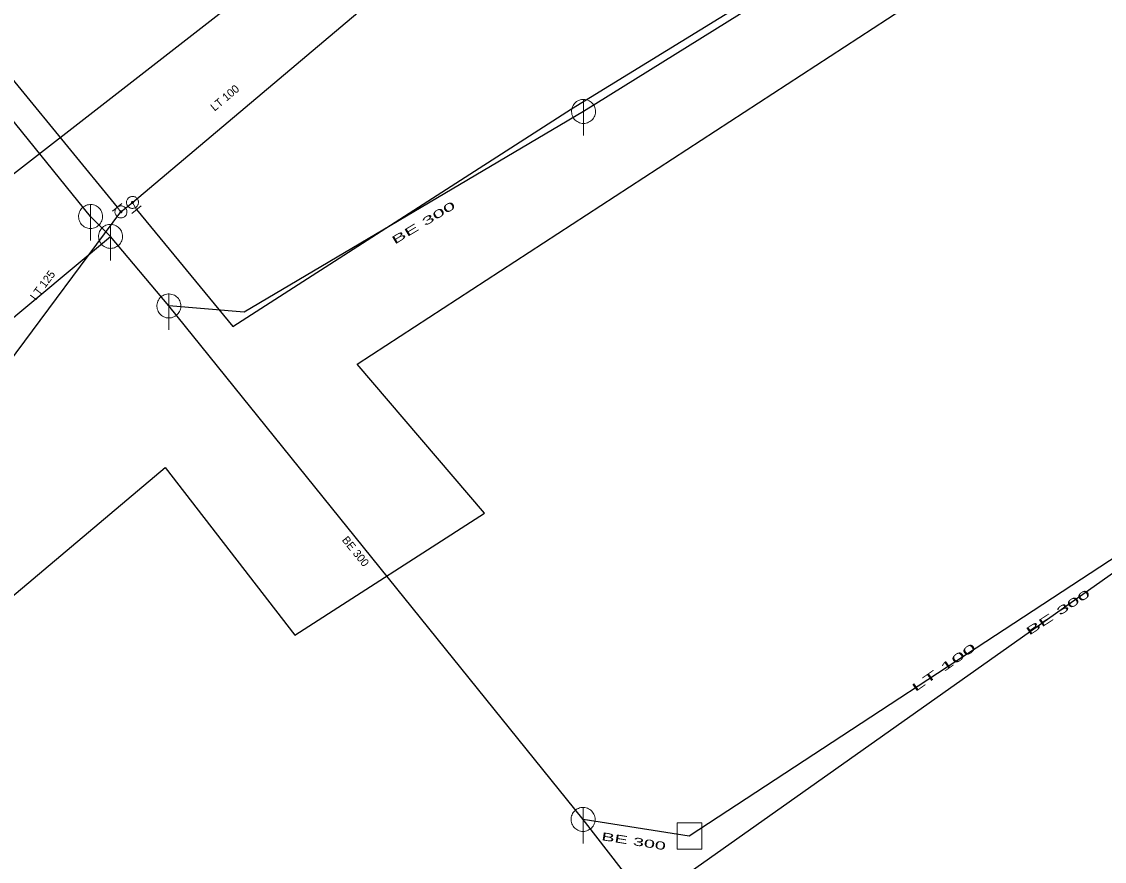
# Model space of a CAD drawing. Extents: x -688296 to -687852, y -973332 to -972816.
# Drawn here: x -688073 to -687982.8, y -973181.4 to -973111.5 of the extents above; entities that cross this region are included whole.
import ezdxf
from ezdxf.enums import TextEntityAlignment as Align

# ---------------------------------------------------------------- set-up
doc = ezdxf.new("R2010")
doc.units = 0
doc.header["$LTSCALE"] = 0.27
for name, color, linetype, lineweight in [('1', 7, 'Continuous', 25), ('14', 7, 'Continuous', 13), ('17', 7, 'Continuous', 25), ('22', 7, 'Continuous', 13), ('34', 7, 'Continuous', 13), ('47', 7, 'Continuous', 13)]:
    doc.layers.add(name, color=color, linetype=linetype, lineweight=lineweight)

msp = doc.modelspace()

# ---------------------------------------------------------------- linework, layer by layer
at = {"layer": '1'}
msp.add_lwpolyline([(-688090.469, -973137.197), (-688100.452, -973146.564), (-688079.864, -973164.439), (-688061.035, -973148.602), (-688050.242, -973162.551), (-688034.437, -973152.412), (-688045.047, -973140.009), (-687999.652, -973110.475), (-688005.19, -973097.204), (-688023.258, -973110.095), (-688049.335, -973105.21)], close=True, dxfattribs=at)
at = {"layer": '14', "lineweight": 25}
for p, q in [((-687989.249, -973096), (-688026.18, -973118.949)), ((-688067.26, -973127.699), (-688080.03, -973111.949)), ((-688104.189, -973161.57), (-688065.592, -973129.356)), ((-688026.221, -973177.902), (-688060.734, -973135.15)), ((-687957.712, -973140.243), (-688017.39, -973179.289)), ((-688021.994, -973183.349), (-688026.221, -973177.902)), ((-688017.39, -973179.289), (-688026.221, -973177.902))]:
    msp.add_line(p, q, dxfattribs=at)
at = {"layer": '14'}
for p, q in [((-688065.039, -973126.929), (-688064.727, -973127.319)), ((-688063.767, -973126.529), (-688063.439, -973127.129))]:
    msp.add_line(p, q, dxfattribs=at)
at = {"layer": '14', "lineweight": 25}
msp.add_lwpolyline([(-688026.18, -973118.95), (-688054.456, -973135.671), (-688060.734, -973135.15), (-688065.592, -973129.356), (-688067.26, -973127.7)], dxfattribs=at)
at = {"layer": '17'}
for points in [[(-688114.989, -973066.03), (-688114.73, -973066.289), (-688065.039, -973126.929)], [(-688063.439, -973127.129), (-688055.41, -973136.87), (-688027.175, -973118.732), (-687991.487, -973096.813), (-687978.252, -973089.283), (-687949, -973074.559)], [(-688063.767, -973126.529), (-688044.978, -973110.715), (-688043.984, -973109.795)], [(-688074.089, -973139.909), (-688064.727, -973127.319), (-688063.767, -973126.529)], [(-687987.568, -973219.849), (-688011, -973191.963), (-688018.429, -973183.079), (-687972.436, -973150.573)]]:
    msp.add_lwpolyline(points, dxfattribs=at)
at = {"layer": '22'}
for p, q in [((-688026.18, -973120.95), (-688026.179, -973117.95)), ((-688067.26, -973129.699), (-688067.259, -973126.699)), ((-688065.592, -973131.356), (-688065.591, -973128.356)), ((-688060.734, -973137.15), (-688060.733, -973134.15)), ((-688026.221, -973179.902), (-688026.22, -973176.902))]:
    msp.add_line(p, q, dxfattribs=at)
for points in [[(-688025.18, -973118.95), (-688025.185, -973118.841), (-688025.203, -973118.733), (-688025.233, -973118.627), (-688025.273, -973118.526), (-688025.325, -973118.429), (-688025.387, -973118.339), (-688025.459, -973118.256), (-688025.539, -973118.182), (-688025.627, -973118.116), (-688025.721, -973118.061), (-688025.821, -973118.016), (-688025.926, -973117.983), (-688026.033, -973117.961), (-688026.142, -973117.951), (-688026.252, -973117.953), (-688026.36, -973117.967), (-688026.467, -973117.992), (-688026.57, -973118.029), (-688026.668, -973118.078), (-688026.76, -973118.136), (-688026.846, -973118.205), (-688026.923, -973118.282), (-688026.992, -973118.368), (-688027.051, -973118.46), (-688027.099, -973118.558), (-688027.136, -973118.661), (-688027.162, -973118.768), (-688027.176, -973118.876), (-688027.179, -973118.986), (-688027.169, -973119.095), (-688027.148, -973119.202), (-688027.114, -973119.306), (-688027.07, -973119.406), (-688027.015, -973119.501), (-688026.949, -973119.589), (-688026.875, -973119.669), (-688026.792, -973119.741), (-688026.702, -973119.803), (-688026.606, -973119.855), (-688026.504, -973119.896), (-688026.399, -973119.926), (-688026.291, -973119.944), (-688026.181, -973119.95), (-688026.072, -973119.944), (-688025.964, -973119.926), (-688025.859, -973119.897), (-688025.757, -973119.856), (-688025.66, -973119.804), (-688025.57, -973119.742), (-688025.487, -973119.671), (-688025.412, -973119.591), (-688025.347, -973119.503), (-688025.291, -973119.409), (-688025.247, -973119.309), (-688025.213, -973119.205), (-688025.191, -973119.097), (-688025.181, -973118.988)], [(-688066.26, -973127.699), (-688066.265, -973127.59), (-688066.283, -973127.482), (-688066.313, -973127.376), (-688066.353, -973127.275), (-688066.405, -973127.178), (-688066.467, -973127.088), (-688066.539, -973127.005), (-688066.619, -973126.931), (-688066.707, -973126.865), (-688066.801, -973126.81), (-688066.901, -973126.765), (-688067.006, -973126.732), (-688067.113, -973126.71), (-688067.222, -973126.7), (-688067.332, -973126.702), (-688067.44, -973126.716), (-688067.547, -973126.741), (-688067.65, -973126.778), (-688067.748, -973126.827), (-688067.84, -973126.885), (-688067.926, -973126.954), (-688068.003, -973127.031), (-688068.072, -973127.117), (-688068.131, -973127.209), (-688068.179, -973127.307), (-688068.216, -973127.41), (-688068.242, -973127.517), (-688068.256, -973127.625), (-688068.259, -973127.735), (-688068.249, -973127.844), (-688068.228, -973127.951), (-688068.194, -973128.055), (-688068.15, -973128.155), (-688068.095, -973128.25), (-688068.029, -973128.338), (-688067.955, -973128.418), (-688067.872, -973128.49), (-688067.782, -973128.552), (-688067.686, -973128.604), (-688067.584, -973128.645), (-688067.479, -973128.675), (-688067.371, -973128.693), (-688067.261, -973128.699), (-688067.152, -973128.693), (-688067.044, -973128.675), (-688066.939, -973128.646), (-688066.837, -973128.605), (-688066.74, -973128.553), (-688066.65, -973128.491), (-688066.567, -973128.42), (-688066.492, -973128.34), (-688066.427, -973128.252), (-688066.371, -973128.158), (-688066.327, -973128.058), (-688066.293, -973127.954), (-688066.271, -973127.846), (-688066.261, -973127.737)], [(-688064.592, -973129.356), (-688064.597, -973129.247), (-688064.615, -973129.139), (-688064.645, -973129.033), (-688064.685, -973128.932), (-688064.737, -973128.835), (-688064.799, -973128.745), (-688064.871, -973128.662), (-688064.951, -973128.588), (-688065.039, -973128.522), (-688065.133, -973128.467), (-688065.233, -973128.422), (-688065.338, -973128.389), (-688065.445, -973128.367), (-688065.554, -973128.357), (-688065.664, -973128.359), (-688065.772, -973128.373), (-688065.879, -973128.398), (-688065.982, -973128.435), (-688066.08, -973128.484), (-688066.172, -973128.542), (-688066.258, -973128.611), (-688066.335, -973128.688), (-688066.404, -973128.774), (-688066.463, -973128.866), (-688066.511, -973128.964), (-688066.548, -973129.067), (-688066.574, -973129.174), (-688066.588, -973129.282), (-688066.591, -973129.392), (-688066.581, -973129.501), (-688066.56, -973129.608), (-688066.526, -973129.712), (-688066.482, -973129.812), (-688066.427, -973129.907), (-688066.361, -973129.995), (-688066.287, -973130.075), (-688066.204, -973130.147), (-688066.114, -973130.209), (-688066.018, -973130.261), (-688065.916, -973130.302), (-688065.811, -973130.332), (-688065.703, -973130.35), (-688065.593, -973130.356), (-688065.484, -973130.35), (-688065.376, -973130.332), (-688065.271, -973130.303), (-688065.169, -973130.262), (-688065.072, -973130.21), (-688064.982, -973130.148), (-688064.899, -973130.077), (-688064.824, -973129.997), (-688064.759, -973129.909), (-688064.703, -973129.815), (-688064.659, -973129.715), (-688064.625, -973129.611), (-688064.603, -973129.503), (-688064.593, -973129.394)], [(-688059.734, -973135.15), (-688059.739, -973135.041), (-688059.757, -973134.933), (-688059.787, -973134.827), (-688059.827, -973134.726), (-688059.879, -973134.629), (-688059.941, -973134.539), (-688060.013, -973134.456), (-688060.093, -973134.382), (-688060.181, -973134.316), (-688060.275, -973134.261), (-688060.375, -973134.216), (-688060.48, -973134.183), (-688060.587, -973134.161), (-688060.696, -973134.151), (-688060.806, -973134.153), (-688060.914, -973134.167), (-688061.021, -973134.192), (-688061.124, -973134.229), (-688061.222, -973134.278), (-688061.314, -973134.336), (-688061.4, -973134.405), (-688061.477, -973134.482), (-688061.546, -973134.568), (-688061.605, -973134.66), (-688061.653, -973134.758), (-688061.69, -973134.861), (-688061.716, -973134.968), (-688061.73, -973135.076), (-688061.733, -973135.186), (-688061.723, -973135.295), (-688061.702, -973135.402), (-688061.668, -973135.506), (-688061.624, -973135.606), (-688061.569, -973135.701), (-688061.503, -973135.789), (-688061.429, -973135.869), (-688061.346, -973135.941), (-688061.256, -973136.003), (-688061.16, -973136.055), (-688061.058, -973136.096), (-688060.953, -973136.126), (-688060.845, -973136.144), (-688060.735, -973136.15), (-688060.626, -973136.144), (-688060.518, -973136.126), (-688060.413, -973136.097), (-688060.311, -973136.056), (-688060.214, -973136.004), (-688060.124, -973135.942), (-688060.041, -973135.871), (-688059.966, -973135.791), (-688059.901, -973135.703), (-688059.845, -973135.609), (-688059.801, -973135.509), (-688059.767, -973135.405), (-688059.745, -973135.297), (-688059.735, -973135.188)], [(-688025.221, -973177.902), (-688025.226, -973177.793), (-688025.244, -973177.685), (-688025.274, -973177.579), (-688025.314, -973177.478), (-688025.366, -973177.381), (-688025.428, -973177.291), (-688025.5, -973177.208), (-688025.58, -973177.134), (-688025.668, -973177.068), (-688025.762, -973177.013), (-688025.862, -973176.968), (-688025.967, -973176.935), (-688026.074, -973176.913), (-688026.183, -973176.903), (-688026.293, -973176.905), (-688026.401, -973176.919), (-688026.508, -973176.944), (-688026.611, -973176.981), (-688026.709, -973177.03), (-688026.801, -973177.088), (-688026.887, -973177.157), (-688026.964, -973177.234), (-688027.033, -973177.32), (-688027.092, -973177.412), (-688027.14, -973177.51), (-688027.177, -973177.613), (-688027.203, -973177.72), (-688027.217, -973177.828), (-688027.22, -973177.938), (-688027.21, -973178.047), (-688027.189, -973178.154), (-688027.155, -973178.258), (-688027.111, -973178.358), (-688027.056, -973178.453), (-688026.99, -973178.541), (-688026.916, -973178.621), (-688026.833, -973178.693), (-688026.743, -973178.755), (-688026.647, -973178.807), (-688026.545, -973178.848), (-688026.44, -973178.878), (-688026.332, -973178.896), (-688026.222, -973178.902), (-688026.113, -973178.896), (-688026.005, -973178.878), (-688025.9, -973178.849), (-688025.798, -973178.808), (-688025.701, -973178.756), (-688025.611, -973178.694), (-688025.528, -973178.623), (-688025.453, -973178.543), (-688025.388, -973178.455), (-688025.332, -973178.361), (-688025.288, -973178.261), (-688025.254, -973178.157), (-688025.232, -973178.049), (-688025.222, -973177.94)], [(-688018.37, -973178.199), (-688016.337, -973178.199), (-688016.337, -973180.392), (-688018.37, -973180.392)]]:
    msp.add_lwpolyline(points, close=True, dxfattribs=at)
at = {"layer": '34'}
for p, q in [((-688064.652, -973126.611), (-688065.425, -973127.245)), ((-688063.053, -973126.81), (-688063.825, -973127.446))]:
    msp.add_line(p, q, dxfattribs=at)
at = {"layer": '47'}
for points in [[(-688063.527, -973126.967), (-688063.482, -973126.94), (-688063.441, -973126.908), (-688063.404, -973126.871), (-688063.369, -973126.832), (-688063.339, -973126.789), (-688063.315, -973126.742), (-688063.295, -973126.694), (-688063.281, -973126.644), (-688063.271, -973126.593), (-688063.267, -973126.54), (-688063.268, -973126.487), (-688063.276, -973126.436), (-688063.288, -973126.385), (-688063.305, -973126.336), (-688063.328, -973126.289), (-688063.355, -973126.244), (-688063.387, -973126.203), (-688063.424, -973126.165), (-688063.463, -973126.131), (-688063.506, -973126.101), (-688063.553, -973126.077), (-688063.602, -973126.057), (-688063.652, -973126.042), (-688063.703, -973126.032), (-688063.755, -973126.029), (-688063.808, -973126.03), (-688063.86, -973126.037), (-688063.91, -973126.05), (-688063.959, -973126.067), (-688064.006, -973126.09), (-688064.051, -973126.117), (-688064.092, -973126.149), (-688064.131, -973126.185), (-688064.164, -973126.225), (-688064.194, -973126.268), (-688064.219, -973126.314), (-688064.239, -973126.363), (-688064.254, -973126.413), (-688064.263, -973126.465), (-688064.266, -973126.517), (-688064.265, -973126.57), (-688064.259, -973126.621), (-688064.245, -973126.672), (-688064.228, -973126.721), (-688064.205, -973126.768), (-688064.178, -973126.813), (-688064.146, -973126.854), (-688064.11, -973126.892), (-688064.07, -973126.926), (-688064.027, -973126.956), (-688063.981, -973126.981), (-688063.933, -973127), (-688063.882, -973127.015), (-688063.831, -973127.024), (-688063.778, -973127.028), (-688063.725, -973127.027), (-688063.675, -973127.02), (-688063.623, -973127.007), (-688063.574, -973126.99)], [(-688064.487, -973127.757), (-688064.442, -973127.73), (-688064.401, -973127.698), (-688064.364, -973127.661), (-688064.329, -973127.622), (-688064.299, -973127.579), (-688064.275, -973127.532), (-688064.255, -973127.484), (-688064.241, -973127.434), (-688064.231, -973127.383), (-688064.227, -973127.33), (-688064.228, -973127.277), (-688064.236, -973127.226), (-688064.248, -973127.175), (-688064.265, -973127.126), (-688064.288, -973127.079), (-688064.315, -973127.034), (-688064.347, -973126.993), (-688064.384, -973126.955), (-688064.423, -973126.921), (-688064.466, -973126.891), (-688064.513, -973126.867), (-688064.562, -973126.847), (-688064.612, -973126.832), (-688064.663, -973126.822), (-688064.715, -973126.819), (-688064.768, -973126.82), (-688064.82, -973126.827), (-688064.87, -973126.84), (-688064.919, -973126.857), (-688064.966, -973126.88), (-688065.011, -973126.907), (-688065.052, -973126.939), (-688065.091, -973126.975), (-688065.124, -973127.015), (-688065.154, -973127.058), (-688065.179, -973127.104), (-688065.199, -973127.153), (-688065.214, -973127.203), (-688065.223, -973127.255), (-688065.226, -973127.307), (-688065.225, -973127.36), (-688065.219, -973127.411), (-688065.205, -973127.462), (-688065.188, -973127.511), (-688065.165, -973127.558), (-688065.138, -973127.603), (-688065.106, -973127.644), (-688065.07, -973127.682), (-688065.03, -973127.716), (-688064.987, -973127.746), (-688064.941, -973127.771), (-688064.893, -973127.79), (-688064.842, -973127.805), (-688064.791, -973127.814), (-688064.738, -973127.818), (-688064.685, -973127.817), (-688064.635, -973127.81), (-688064.583, -973127.797), (-688064.534, -973127.78)], [(-688063.727, -973126.6), (-688063.719, -973126.596), (-688063.713, -973126.591), (-688063.707, -973126.585), (-688063.702, -973126.578), (-688063.696, -973126.571), (-688063.693, -973126.563), (-688063.689, -973126.556), (-688063.687, -973126.547), (-688063.686, -973126.539), (-688063.685, -973126.53), (-688063.685, -973126.521), (-688063.686, -973126.513), (-688063.688, -973126.505), (-688063.69, -973126.497), (-688063.695, -973126.489), (-688063.699, -973126.481), (-688063.704, -973126.475), (-688063.71, -973126.469), (-688063.717, -973126.464), (-688063.724, -973126.458), (-688063.732, -973126.455), (-688063.739, -973126.451), (-688063.748, -973126.449), (-688063.757, -973126.447), (-688063.765, -973126.447), (-688063.774, -973126.447), (-688063.782, -973126.448), (-688063.79, -973126.45), (-688063.798, -973126.452), (-688063.806, -973126.457), (-688063.814, -973126.461), (-688063.82, -973126.466), (-688063.826, -973126.472), (-688063.831, -973126.479), (-688063.837, -973126.486), (-688063.841, -973126.493), (-688063.844, -973126.501), (-688063.846, -973126.51), (-688063.848, -973126.519), (-688063.848, -973126.527), (-688063.848, -973126.536), (-688063.847, -973126.544), (-688063.845, -973126.552), (-688063.843, -973126.56), (-688063.838, -973126.568), (-688063.834, -973126.576), (-688063.829, -973126.582), (-688063.823, -973126.588), (-688063.816, -973126.593), (-688063.809, -973126.599), (-688063.802, -973126.603), (-688063.794, -973126.606), (-688063.785, -973126.608), (-688063.777, -973126.609), (-688063.768, -973126.61), (-688063.759, -973126.61), (-688063.751, -973126.609), (-688063.743, -973126.607), (-688063.735, -973126.605)], [(-688064.687, -973127.39), (-688064.679, -973127.386), (-688064.673, -973127.381), (-688064.667, -973127.375), (-688064.662, -973127.368), (-688064.656, -973127.361), (-688064.653, -973127.353), (-688064.649, -973127.346), (-688064.647, -973127.337), (-688064.646, -973127.329), (-688064.645, -973127.32), (-688064.645, -973127.311), (-688064.646, -973127.303), (-688064.648, -973127.295), (-688064.65, -973127.287), (-688064.655, -973127.279), (-688064.659, -973127.271), (-688064.664, -973127.265), (-688064.67, -973127.259), (-688064.677, -973127.254), (-688064.684, -973127.248), (-688064.692, -973127.245), (-688064.699, -973127.241), (-688064.708, -973127.239), (-688064.717, -973127.237), (-688064.725, -973127.237), (-688064.734, -973127.237), (-688064.742, -973127.238), (-688064.75, -973127.24), (-688064.758, -973127.242), (-688064.766, -973127.247), (-688064.774, -973127.251), (-688064.78, -973127.256), (-688064.786, -973127.262), (-688064.791, -973127.269), (-688064.797, -973127.276), (-688064.801, -973127.283), (-688064.804, -973127.291), (-688064.806, -973127.3), (-688064.808, -973127.309), (-688064.808, -973127.317), (-688064.808, -973127.326), (-688064.807, -973127.334), (-688064.805, -973127.342), (-688064.803, -973127.35), (-688064.798, -973127.358), (-688064.794, -973127.366), (-688064.789, -973127.372), (-688064.783, -973127.378), (-688064.776, -973127.383), (-688064.769, -973127.389), (-688064.762, -973127.393), (-688064.754, -973127.396), (-688064.745, -973127.398), (-688064.737, -973127.399), (-688064.728, -973127.4), (-688064.719, -973127.4), (-688064.711, -973127.399), (-688064.703, -973127.397), (-688064.695, -973127.395)]]:
    msp.add_lwpolyline(points, close=True, dxfattribs=at)

# ---------------------------------------------------------------- texts
at = {"layer": '1'}
for s, rotation, p in [('LT 100', 40, (-688055.8622, -973118.0777)), ('LT 100', 40, (-688055.8622, -973118.0777)), ('LT 100', 40, (-688055.8622, -973118.0777)), ('LT 100', 40, (-688055.8622, -973118.0777)), ('LT 100', 40, (-688055.8622, -973118.0777)), ('LT 125', 53, (-688070.9917, -973133.6229)), ('LT 125', 53, (-688070.9917, -973133.6229)), ('LT 125', 53, (-688070.9917, -973133.6229)), ('LT 125', 53, (-688070.9917, -973133.6229)), ('LT 125', 53, (-688070.9917, -973133.6229)), ('BE 300', 309, (-688045.4337, -973155.7908)), ('BE 300', 309, (-688045.4337, -973155.7908)), ('BE 300', 309, (-688045.4337, -973155.7908)), ('BE 300', 309, (-688045.4337, -973155.7908)), ('BE 300', 309, (-688045.4337, -973155.7908))]:
    msp.add_text(s, height=0.6667, rotation=rotation, dxfattribs=at).set_placement(p, align=Align.CENTER)
for s, rotation, width, p in [('BE 300', 31, 2.05, (-688039.3507, -973128.5036)), ('BE 300', 31, 2.05, (-688039.3507, -973128.5036)), ('BE 300', 31, 2.05, (-688039.3507, -973128.5036)), ('BE 300', 31, 2.05, (-688039.3507, -973128.5036)), ('BE 300', 31, 2.05, (-688039.3507, -973128.5036)), ('BE 300', 33, 2.1, (-687986.4705, -973160.9362)), ('BE 300', 33, 2.1, (-687986.4705, -973160.9362)), ('BE 300', 33, 2.1, (-687986.4705, -973160.9362)), ('BE 300', 33, 2.1, (-687986.4705, -973160.9362)), ('BE 300', 33, 2.1, (-687986.4705, -973160.9362)), ('LT 100', 35, 2.25, (-687995.9782, -973165.5209)), ('LT 100', 35, 2.25, (-687995.9782, -973165.5209)), ('LT 100', 35, 2.25, (-687995.9782, -973165.5209)), ('LT 100', 35, 2.25, (-687995.9782, -973165.5209)), ('LT 100', 35, 2.25, (-687995.9782, -973165.5209)), ('BE 300', 351, 1.85, (-688022.0531, -973180.047)), ('BE 300', 351, 1.85, (-688022.0531, -973180.047)), ('BE 300', 351, 1.85, (-688022.0531, -973180.047)), ('BE 300', 351, 1.85, (-688022.0531, -973180.047)), ('BE 300', 351, 1.85, (-688022.0531, -973180.047))]:
    msp.add_text(s, height=0.6667, rotation=rotation, dxfattribs=dict(at, width=width)).set_placement(p, align=Align.CENTER)

doc.saveas('drawing.dxf')
